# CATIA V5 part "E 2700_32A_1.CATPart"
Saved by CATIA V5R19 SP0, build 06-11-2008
Definition: E 2700_32A_1
Nomenclature: E 2700_32A_1
Description: PART--DESC
Material "Plastic": density 1200 kg/m3, Young's modulus 2.2e+09 Pa, Poisson ratio 0.38, thermal expansion 6.84e-05 1/K
Bounding box of the stored display mesh (mm): x -36.2 to 36.2, y -11.4 to 11.4, z -11.5 to 18.6
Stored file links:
  G:\UTB\Kombinované\Bakalářská práce\Catia\FORMA\E 2700_32A_1.CATPart
  D:\Aplikace\CATIA\Nová složka\win_b64\startup\materials\Catalog.CATMaterial
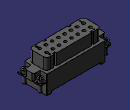
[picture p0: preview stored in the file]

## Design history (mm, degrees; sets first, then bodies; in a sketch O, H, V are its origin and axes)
Body1 "E 2700_32A" (main body)
  Solid1: solid without history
